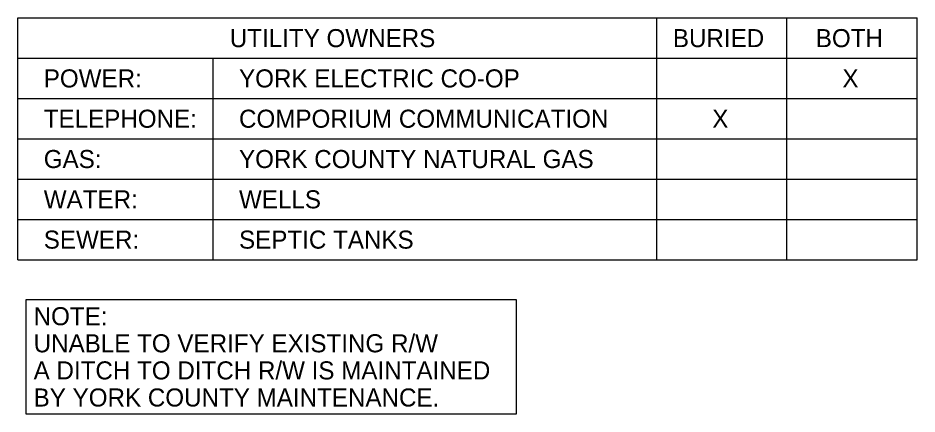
# Model space of a CAD drawing. Extents: x 1964853 to 1967410, y 1117103 to 1120421.
# Drawn here: x 1965761 to 1966059.4, y 1117961 to 1118092.5 of the extents above; entities that cross this region are included whole.
import ezdxf

# ---------------------------------------------------------------- set-up
doc = ezdxf.new("R2010")
doc.units = 0
for name, color, linetype in [('Level 13', 7, 'Continuous'), ('Level 24', 7, 'Continuous'), ('Level 41', 7, 'Continuous')]:
    doc.layers.add(name, color=color, linetype=linetype)

msp = doc.modelspace()

# ---------------------------------------------------------------- linework, layer by layer
at = {"layer": 'Level 24'}
msp.add_line((1965761.02, 1118092.54), (1965761.02, 1118092.54), dxfattribs=at)
at = {"layer": 'Level 41'}
for p, q in [((1965761.02, 1118012.21), (1965761.02, 1118092.54)), ((1965761.02, 1118092.54), (1965972.97, 1118092.54)), ((1965972.97, 1118012.21), (1965972.97, 1118092.54)), ((1965972.97, 1118092.54), (1966059.37, 1118092.54)), ((1966016.17, 1118012.21), (1966016.17, 1118092.54)), ((1966059.37, 1118012.21), (1966059.37, 1118092.54)), ((1965761.02, 1118079.15), (1965972.97, 1118079.15)), ((1965761.02, 1118079.15), (1965825.82, 1118079.15)), ((1965825.82, 1118012.21), (1965825.82, 1118079.15)), ((1965825.82, 1118012.21), (1965825.82, 1118079.15)), ((1965825.82, 1118079.15), (1966059.37, 1118079.15)), ((1965761.02, 1118065.76), (1965825.82, 1118065.76)), ((1965761.02, 1118065.76), (1965825.82, 1118065.76)), ((1965825.82, 1118065.76), (1965972.97, 1118065.76)), ((1965825.82, 1118065.76), (1966059.37, 1118065.76)), ((1965761.02, 1118052.37), (1965825.82, 1118052.37)), ((1965761.02, 1118052.37), (1965825.82, 1118052.37)), ((1965825.82, 1118052.37), (1965972.97, 1118052.37)), ((1965825.82, 1118052.37), (1966059.37, 1118052.37)), ((1965761.02, 1118038.99), (1965825.82, 1118038.99)), ((1965761.02, 1118038.99), (1965825.82, 1118038.99)), ((1965825.82, 1118038.99), (1965972.97, 1118038.99)), ((1965825.82, 1118038.99), (1966059.37, 1118038.99)), ((1965761.02, 1118025.6), (1965825.82, 1118025.6)), ((1965761.02, 1118025.6), (1965825.82, 1118025.6)), ((1965825.82, 1118025.6), (1965972.97, 1118025.6)), ((1965825.82, 1118025.6), (1966059.37, 1118025.6)), ((1965761.02, 1118012.21), (1965825.82, 1118012.21)), ((1965825.82, 1118012.21), (1965972.97, 1118012.21)), ((1965972.97, 1118012.21), (1966059.37, 1118012.21))]:
    msp.add_line(p, q, dxfattribs=at)
msp.add_lwpolyline([(1965763.71, 1117998.97), (1965926.29, 1117998.97), (1965926.29, 1117960.97), (1965763.71, 1117960.97)], close=True, dxfattribs=at)

# ---------------------------------------------------------------- texts
at = {"layer": 'Level 13'}
for s, p in [('NOTE:', (1965766.21, 1117990.47)), ('UNABLE TO VERIFY EXISTING R/W', (1965766.21, 1117981.47)), ('A DITCH TO DITCH R/W IS MAINTAINED', (1965766.21, 1117972.47)), ('BY YORK COUNTY MAINTENANCE.', (1965766.21, 1117963.47))]:
    msp.add_text(s, height=6, dxfattribs=at).set_placement(p)
at = {"layer": 'Level 41'}
for s, p in [(' UTILITY OWNERS', (1965829.08, 1118082.84)), ('BURIED', (1965978.34, 1118082.84)), ('BOTH', (1966025.77, 1118082.84)), ('POWER:', (1965769.57, 1118069.46)), ('YORK ELECTRIC CO-OP', (1965834.37, 1118069.46)), ('X', (1966034.61, 1118069.46)), ('TELEPHONE:', (1965769.57, 1118056.07)), ('COMPORIUM COMMUNICATION', (1965834.37, 1118056.07)), ('X', (1965991.41, 1118056.07)), ('GAS:', (1965769.57, 1118042.68)), ('YORK COUNTY NATURAL GAS', (1965834.37, 1118042.68)), ('WATER:', (1965769.57, 1118029.29)), ('WELLS', (1965834.37, 1118029.29)), ('SEWER:', (1965769.57, 1118015.91)), ('SEPTIC TANKS', (1965834.37, 1118015.91))]:
    msp.add_text(s, height=6, dxfattribs=at).set_placement(p)

doc.saveas('drawing.dxf')
